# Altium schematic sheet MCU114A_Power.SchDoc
size 431 x 279 mm; Date: Not shown in title block; ApprovedBy: Not shown in title block; CheckedBy: Not shown in title block; Author: Not shown in title block; CompanyName: Not shown in title block; Engineer: Not shown in title block; Organization: Not shown in title block; Address1: Not shown in title block; Address2: Not shown in title block; Address3: Not shown in title block; Address4: Not shown in title block; DocumentNumber: 5; Revision: Use project parameter SCH_Rev; SheetNumber: 5; SheetTotal: 11; PageSetup: Record=PageOptions¦CenterHorizontal=True¦CenterVertical=True¦PrintScale=1.00¦XCorrection=1.00¦YCorrection=1.00¦PrintKind=0¦BorderSize=5000000¦LeftOffset=0¦BottomOffset=0¦Orientation=2¦PaperLength=1000¦PaperWidth=1000¦Scale=100¦PaperSource=15¦PrintQuality=600¦MediaType=1¦DitherType=10¦PaperKind=Letter¦PrintScaleMode=1
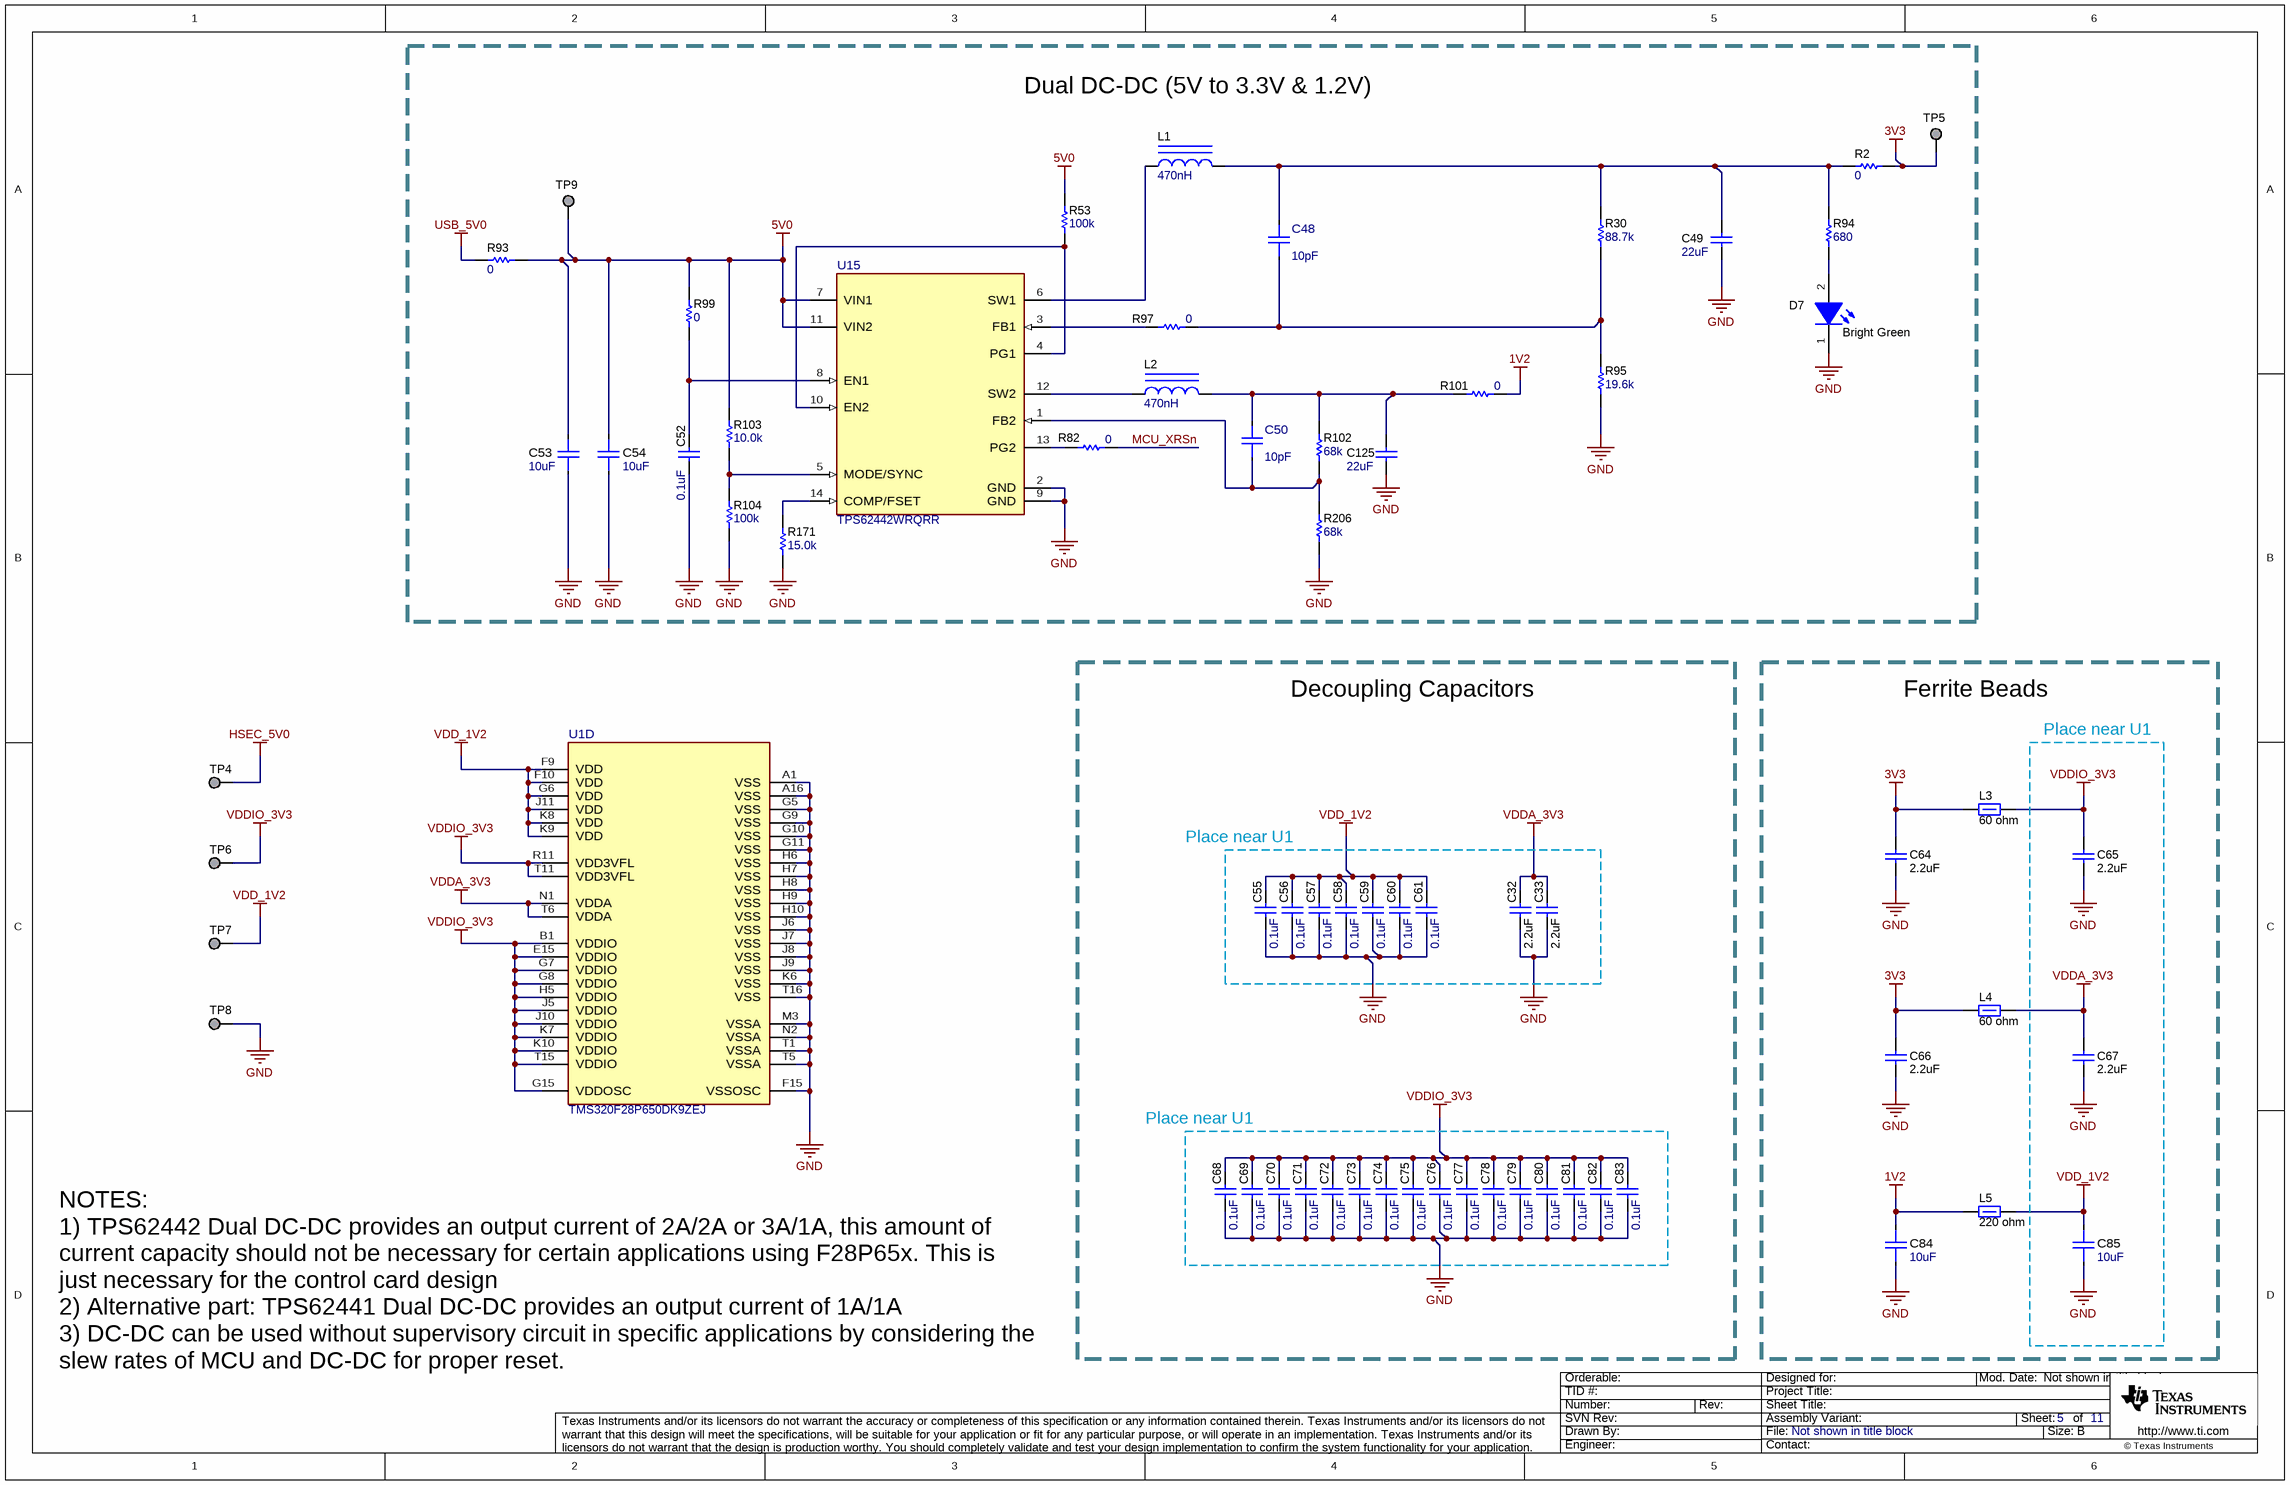
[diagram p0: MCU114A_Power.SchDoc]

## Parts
C32  ValueDisplayed: 2.2uF  [0603]  (hidden comment: 885012106018)
C33  ValueDisplayed: 2.2uF  [0603]  (hidden comment: 885012106018)
C48  ValueDisplayed: 10pF  [FP-885012006032_0603-MFG]  (hidden comment: 885012006032)
C49  ValueDisplayed: 22uF  [0603]  (hidden comment: GRM188R61A226ME15D)
C50  ValueDisplayed: 10pF  [FP-885012006032_0603-MFG]  (hidden comment: 885012006032)
C52  ValueDisplayed: 0.1uF  [0402]  (hidden comment: 885012205037)
C53  ValueDisplayed: 10uF  [FP-CC0603KRX5R7BB106_0603-MFG]  (hidden comment: CC0603KRX5R7BB106)
C54  ValueDisplayed: 10uF  [FP-CC0603KRX5R7BB106_0603-MFG]  (hidden comment: CC0603KRX5R7BB106)
C55  ValueDisplayed: 0.1uF  [0402]  (hidden comment: 885012205037)
C56  ValueDisplayed: 0.1uF  [0402]  (hidden comment: 885012205037)
C57  ValueDisplayed: 0.1uF  [0402]  (hidden comment: 885012205037)
C58  ValueDisplayed: 0.1uF  [0402]  (hidden comment: 885012205037)
C59  ValueDisplayed: 0.1uF  [0402]  (hidden comment: 885012205037)
C60  ValueDisplayed: 0.1uF  [0402]  (hidden comment: 885012205037)
C61  ValueDisplayed: 0.1uF  [0402]  (hidden comment: 885012205037)
C64  ValueDisplayed: 2.2uF  [0603]  (hidden comment: 885012106018)
C65  ValueDisplayed: 2.2uF  [0603]  (hidden comment: 885012106018)
C66  ValueDisplayed: 2.2uF  [0603]  (hidden comment: 885012106018)
C67  ValueDisplayed: 2.2uF  [0603]  (hidden comment: 885012106018)
C68  ValueDisplayed: 0.1uF  [0402]  (hidden comment: 885012205037)
C69  ValueDisplayed: 0.1uF  [0402]  (hidden comment: 885012205037)
C70  ValueDisplayed: 0.1uF  [0402]  (hidden comment: 885012205037)
C71  ValueDisplayed: 0.1uF  [0402]  (hidden comment: 885012205037)
C72  ValueDisplayed: 0.1uF  [0402]  (hidden comment: 885012205037)
C73  ValueDisplayed: 0.1uF  [0402]  (hidden comment: 885012205037)
C74  ValueDisplayed: 0.1uF  [0402]  (hidden comment: 885012205037)
C75  ValueDisplayed: 0.1uF  [0402]  (hidden comment: 885012205037)
C76  ValueDisplayed: 0.1uF  [0402]  (hidden comment: 885012205037)
C77  ValueDisplayed: 0.1uF  [0402]  (hidden comment: 885012205037)
C78  ValueDisplayed: 0.1uF  [0402]  (hidden comment: 885012205037)
C79  ValueDisplayed: 0.1uF  [0402]  (hidden comment: 885012205037)
C80  ValueDisplayed: 0.1uF  [0402]  (hidden comment: 885012205037)
C81  ValueDisplayed: 0.1uF  [0402]  (hidden comment: 885012205037)
C82  ValueDisplayed: 0.1uF  [0402]  (hidden comment: 885012205037)
C83  ValueDisplayed: 0.1uF  [0402]  (hidden comment: 885012205037)
C84  ValueDisplayed: 10uF  [FP-CC0603KRX5R7BB106_0603-MFG]  (hidden comment: CC0603KRX5R7BB106)
C85  ValueDisplayed: 10uF  [FP-CC0603KRX5R7BB106_0603-MFG]  (hidden comment: CC0603KRX5R7BB106)
C125  ValueDisplayed: 22uF  [0603]  (hidden comment: GRM188R61A226ME15D)
D7  value Bright Green  [WL-SMCW_Green_0805]  (hidden comment: 150080VS75000)
L1  ValueDisplayed: 470nH  [XFL4015]  (hidden comment: XFL4015-471MEC)
L2  ValueDisplayed: 470nH  [XFL4015]  (hidden comment: XFL4015-471MEC)
L3  60 ohm  [0805_HV]
L4  60 ohm  [0805_HV]
L5  220 ohm  [0805_HV]
R2  ValueDisplayed: 0  [0402]  (hidden comment: ERJ-2GE0R00X)
R30  ValueDisplayed: 88.7k  [0402]  (hidden comment: CRCW040288K7FKED)
R53  ValueDisplayed: 100k  [0603]  (hidden comment: CRCW0603100KJNEA)
R82  ValueDisplayed: 0  [0402]  (hidden comment: ERJ-2GE0R00X)
R93  ValueDisplayed: 0  [0402]  (hidden comment: ERJ-2GE0R00X)
R94  ValueDisplayed: 680  [0402]  (hidden comment: CRCW0402680RJNED)
R95  ValueDisplayed: 19.6k  [0402]  (hidden comment: CRCW040219K6FKED)
R97  ValueDisplayed: 0  [0402]  (hidden comment: ERJ-2GE0R00X)
R99  ValueDisplayed: 0  [0402]  (hidden comment: ERJ-2GE0R00X)
R101  ValueDisplayed: 0  [0402]  (hidden comment: ERJ-2GE0R00X)
R102  ValueDisplayed: 68k  [0402]  (hidden comment: CRCW040268K0JNED)
R103  ValueDisplayed: 10.0k  [0402]  (hidden comment: AC0402FR-0710KL)
R104  ValueDisplayed: 100k  [0603]  (hidden comment: CRCW0603100KJNEA)
R171  ValueDisplayed: 15.0k  [0402]  (hidden comment: CRCW040215K0FKED)
R206  ValueDisplayed: 68k  [0402]  (hidden comment: CRCW040268K0JNED)
TP4  TESTPOINT  [TP_50MIL-25MILHOLE]  (value not drawn)  (no BOM)
TP5  TESTPOINT  [TP_50MIL-25MILHOLE]  (value not drawn)  (no BOM)
TP6  TESTPOINT  [TP_50MIL-25MILHOLE]  (value not drawn)  (no BOM)
TP7  TESTPOINT  [TP_50MIL-25MILHOLE]  (value not drawn)  (no BOM)
TP8  TESTPOINT  [TP_50MIL-25MILHOLE]  (value not drawn)  (no BOM)
TP9  TESTPOINT  [TP_50MIL-25MILHOLE]  (value not drawn)  (no BOM)
U1  TMS320F28P650DK9ZEJ  [ZEJ0256A-MFG]  (part D of 4)
U15  TPS62442WRQRR  [RQR0014A-MFG]

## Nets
1V2: C84.2 L5.1 R101.2
3V3: C64.1 C66.1 L3.1 L4.1 R2.2 TP5.1
5V0: C53.2 C54.2 R53.2 R93.2 R99.2 R103.2 TP9.1 U15.7(VIN1) U15.11(VIN2)
GND: C32.2 C33.2 C49.2 C52.1 C53.1 C54.1 C55.2 C56.2 C57.2 C58.2 C59.2 C60.2 C61.2 C64.2 C65.2 C66.2 C67.2 C68.2 C69.2 C70.2 C71.2 C72.2 C73.2 C74.2 C75.2 C76.2 C77.2 C78.2 C79.2 C80.2 C81.2 C82.2 C83.2 C84.1 C85.1 C125.2 D7.1(K) R95.1 R104.1 R171.1 R206.1 TP8.1 U1.A1(VSS) U1.A16(VSS) U1.F15(VSSOSC) U1.G5(VSS) U1.G9(VSS) U1.G10(VSS) U1.G11(VSS) U1.H6(VSS) U1.H7(VSS) U1.H8(VSS) U1.H9(VSS) U1.H10(VSS) U1.J6(VSS) U1.J7(VSS) U1.J8(VSS) U1.J9(VSS) U1.K6(VSS) U1.M3(VSSA) U1.N2(VSSA) U1.T1(VSSA) U1.T5(VSSA) U1.T16(VSS) U15.2(GND) U15.9(GND)
HSEC_5V0: TP4.1
USB_5V0: R93.1
VDD_1V2: C55.1 C56.1 C57.1 C58.1 C59.1 C60.1 C61.1 C85.2 L5.2 TP7.1 U1.F9(VDD) U1.F10(VDD) U1.G6(VDD) U1.J11(VDD) U1.K8(VDD) U1.K9(VDD)
VDDA_3V3: C32.1 C33.1 C67.1 L4.2 U1.N1(VDDA) U1.T6(VDDA)
VDDIO_3V3: C65.1 C68.1 C69.1 C70.1 C71.1 C72.1 C73.1 C74.1 C75.1 C76.1 C77.1 C78.1 C79.1 C80.1 C81.1 C82.1 C83.1 L3.2 TP6.1 U1.B1(VDDIO) U1.E15(VDDIO) U1.G7(VDDIO) U1.G8(VDDIO) U1.G15(VDDOSC) U1.H5(VDDIO) U1.J5(VDDIO) U1.J10(VDDIO) U1.K7(VDDIO) U1.K10(VDDIO) U1.R11(VDD3VFL) U1.T11(VDD3VFL) U1.T15(VDDIO)
MCU_XRSn: R82.2
NetC48_1: C48.1 R30.1 R95.2 R97.2
NetC48_2: C48.2 C49.1 L1.2 R2.1 R30.2 R94.2
NetC50_1: C50.1 R102.1 R206.2 U15.1(FB2)
NetC50_2: C50.2 C125.1 L2.2 R101.1 R102.2
NetC52_2: C52.2 R99.1 U15.8(EN1)
NetD7_2: D7.2(A) R94.1
NetL1_1: L1.1 U15.6(SW1)
NetL2_1: L2.1 U15.12(SW2)
NetR53_1: R53.1 U15.4(PG1) U15.10(EN2)
NetR82_1: R82.1 U15.13(PG2)
NetR97_1: R97.1 U15.3(FB1)
NetR103_1: R103.1 R104.2 U15.5(MODE/SYNC)
NetR171_2: R171.2 U15.14(COMP/FSET)

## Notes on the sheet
- Dual DC-DC (5V to 3.3V & 1.2V)
- Decoupling Capacitors
- Ferrite Beads
- Place near U1
- NOTES:
  1) TPS62442 Dual DC-DC provides an output current of 2A/2A or 3A/1A, this amount of current capacity should not be necessary for certain applications using F28P65x. This is just necessary for the control card design
  2) Alternative part: TPS62441 Dual DC-DC provides an output current of 1A/1A
  3) DC-DC can be used without supervisory circuit in specific applications by considering the slew rates of MCU and DC-DC for proper reset.

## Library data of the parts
C32 C33 C64-C67 = CMP-0006825-5: CAP, CERM, 2.2 uF, 16 V, +/- 20%, X5R, 0603; Manufacturer: Wurth Elektronik; TaMin_C: -55°C; Polarized: N; SizeAreaWB_mm2: 4.68; Value1: Unknown; U/M: EA; Value: 2.2uF; TaMax_C: 85°C; SizeZ_mm: 1; SizeX_mm: 1.6; SizeY_mm: 0.8; Value2: 16V; SizeArea_mm2: 1.28; Cap_F: 2.2µF; AEC Category: Q200
C48 C50 = CMP-0096972-1: 10 pF ±5% 25V Ceramic Capacitor C0G, NP0 0603 (1608 Metric); Manufacturer: Wurth Electronics; Value: 10pF; AEC Qualified: No; TempCo: 30ppm/°C; SizeZ_mm: 0.87mm
C49 C125 = CMP-0007324-5: CAP, CERM, 22 uF, 10 V, +/- 20%, X5R, 0603; Manufacturer: MuRata; TaMin_C: -55°C; Polarized: N; SizeAreaWB_mm2: 4.68; Value1: Unknown; U/M: EA; Value: 22uF; TaMax_C: 85°C; SizeZ_mm: 1; SizeX_mm: 1.6; SizeY_mm: 0.8; Value2: 10V; SizeArea_mm2: 1.28; Cap_F: 22µF; AEC Category: Q200
C52 C55-C61 C68-C83 = CMP-0006228-2: CAP, CERM, 0.1 uF, 16 V, +/- 10%, X7R, 0402; Manufacturer: Wurth Elektronik; TaMin_C: -55°C; Polarized: N; SizeAreaWB_mm2: 3; Value1: Unknown; U/M: EA; Value: 0.1uF; TaMax_C: 125°C; SizeZ_mm: 0.6; SizeX_mm: 1; SizeY_mm: 0.5; Value2: 16V; Cap_F: 100nF; AEC Category: Q200
C53 C54 C84 C85 = CMP-0001560-1: Multilayer Ceramic Capacitors 10uF 16V X5R 10% SMD 0603 85°C Paper T/R - Tape an; Manufacturer: Yageo; AEC Qualified: No; Cap_F: 10µF; SizeZ_mm: 1mm; TempCo: 15%; Value: 10µF
D7 = CMP-0002960-2: LED, Bright Green, SMD; Manufacturer: Wurth Elektronik; Type: AlInGaP; Vf_V: 2V; Io_A: 20mA; Vr_V: 5V; Tjmax_C: 85°C; Power_TotalModule: 72mW; Value1: 0.072W; Angle: 140; U/M: EA
L1 L2 = CMP-0061147-1: Inductor, Shielded, Composite, 470 nH, 3.5 A, 0.0076 ohm, SMD; Manufacturer: Coilcraft; Isat: 3.5A @ 10% inductance drop; Irms: 9.1A @ 20C rise; Green_Lifecycle: Not Set; SizeAreaWB_mm2: 28.09; DCR_ohm: 7.6m; Green_REACh: Incomplete; Value: 470nH; Imax_A: 3.5A; SizeZ_mm: 1.6; SizeX_mm: 4.3; SizeArea_mm2: 18.49; AEC Category: Q200
L3 L4 = CMP-0003093-1: Ferrite Bead, 60 ohm @ 100 MHz, 3 A, 0805; Manufacturer: Wurth Elektronik; PartNumber: 742792063; Ztyp@1GHz_Ohm: 95.384; ZTyp@100MHz_Ohm: 60; SizeAreaWB_mm2: 6.75; DCR_ohm: 0.025; Value1: 0.025 ohm; Imax_A: 3A; SizeZ_mm: 1.45; SizeX_mm: 2; SizeY_mm: 1.25; SizeArea_mm2: 2.5
L5 = CMP-0003073-1: Ferrite Bead, 220 ohm @ 100 MHz, 2 A, 0805; Manufacturer: Wurth Elektronik; PartNumber: 742792022; Ztyp@1GHz_Ohm: 190.289; ZTyp@100MHz_Ohm: 220; SizeAreaWB_mm2: 6.75; DCR_ohm: 0.05; Value1: 0.05 ohm; Imax_A: 2A; SizeZ_mm: 1.45; SizeX_mm: 2; SizeY_mm: 1.25; SizeArea_mm2: 2.5
R2 R82 R93 R97 R99 R101 = CMP-0026992-3: RES, 0, 5%, 0.1 W, AEC-Q200 Grade 0, 0402; Manufacturer: Panasonic; Power_W: 100mW; TempCo: 600 ppm/C; Value_Code: 0000; Value: 0; EIA_Code: E24; SizeX_mm: 1; SizeY_mm: 0.5; SizeZ_mm: 0.6; Value2: 0.1W; AEC Qualified: Y; VDC_V: 50V; AEC Category: Q200; SizeAreaWB_mm2: 3
R30 = CMP-0026586-2: RES, 88.7 k, 1%, 0.063 W, AEC-Q200 Grade 0, 0402; Manufacturer: Vishay-Dale; Power_W: 63mW; TempCo: 100 ppm/C; Value_Code: 88k7; Value: 88.7k; EIA_Code: E96; SizeX_mm: 1; SizeY_mm: 0.5; SizeZ_mm: 0.6; Value2: 0.063W; AEC Qualified: Y; VDC_V: 50V; AEC Category: Q200; AEC Grade: 0
R53 R104 = CMP-0025698-4: RES, 100 k, 5%, 0.1 W, AEC-Q200 Grade 0, 0603; Manufacturer: Vishay-Dale; Power_W: 100mW; TempCo: 200 ppm/C; Value: 100k; EIA_Code: E24; SizeX_mm: 1.6; SizeY_mm: 0.8; SizeZ_mm: 1; Value2: 0.1W; SizeArea_mm2: 1.28; AEC Qualified: Y; VDC_V: 75V; AEC Category: Q200; AEC Grade: 0
R94 = CMP-0026962-3: RES, 680, 5%, 0.063 W, AEC-Q200 Grade 0, 0402; Manufacturer: Vishay-Dale; Power_W: 63mW; TempCo: 200 ppm/C; Value_Code: 680R; Value: 680; EIA_Code: E24; SizeX_mm: 1; SizeY_mm: 0.5; SizeZ_mm: 0.6; Value2: 0.063W; AEC Qualified: Y; VDC_V: 50V; AEC Category: Q200; AEC Grade: 0
R95 = CMP-0026068-3: RES, 19.6 k, 1%, 0.063 W, AEC-Q200 Grade 0, 0402; Manufacturer: Vishay-Dale; Power_W: 63mW; TempCo: 100 ppm/C; Value_Code: 19k6; Value: 19.6k; EIA_Code: E96; SizeX_mm: 1; SizeY_mm: 0.5; SizeZ_mm: 0.6; Value2: 0.063W; AEC Qualified: Y; VDC_V: 50V; AEC Category: Q200; AEC Grade: 0
R102 R206 = CMP-0026963-3: RES, 68 k, 5%, 0.063 W, AEC-Q200 Grade 0, 0402; Manufacturer: Vishay-Dale; Power_W: 63mW; TempCo: 200 ppm/C; Value_Code: 68k0; Value: 68k; EIA_Code: E24; SizeX_mm: 1; SizeY_mm: 0.5; SizeZ_mm: 0.6; Value2: 0.063W; AEC Qualified: Y; VDC_V: 50V; AEC Category: Q200; AEC Grade: 0
R103 = CMP-0077731-1: RES, 10.0 k, 1%, 0.063 W, AEC-Q200 Grade 0, 0402; Manufacturer: Yageo America; Power_W: 63mW; TempCo: 100 ppm/C; Value_Code: 10k0; U/M: EA; Value: 10.0k; EIA_Code: E96; Res_ohm: 10k; SizeX_mm: 1.0; SizeY_mm: 0.5; SizeZ_mm: 0.6; Value2: 0.063W; AEC Qualified: Y; VDC_V: 50V; AEC Grade: 0; AEC Category: Q200
R171 = CMP-0026027-3: RES, 15.0 k, 1%, 0.063 W, AEC-Q200 Grade 0, 0402; Manufacturer: Vishay-Dale; Power_W: 63mW; TempCo: 100 ppm/C; Value_Code: 15k0; Value: 15.0k; EIA_Code: E96; Res_ohm: 15k; SizeX_mm: 1; SizeY_mm: 0.5; SizeZ_mm: 0.6; Value2: 0.063W; AEC Qualified: Y; VDC_V: 50V; AEC Category: Q200; AEC Grade: 0
TP4-TP9 = CMP-0078143-3: TEST POINT.  No entry in BOM.
U1 = CMP-0096042-2: Real-Time Microcontroller NFBGA256; Manufacturer: Texas Instruments; AEC Category: Q200; Core Architecture: C28x; Data Bus Width: 32bits; Number Of Ethernet Channels: 1; Number Of Cores: 2; CompType: IC; Number Of I/Os: 159; Interface: I2C,SPI,UART,CAN,USB,LIN,SCI,Ethernet,Other; Number Of Pwm Channels: 36; AEC Qualified: No; Number Of Timers/Counters: 6; Standoff Height: 0.35mm; Number Of Spi Channels: 4; SizeZ_mm: 1.4mm; Number Of Adc Channels: 40; Ram Size: 248KBytes; Frequency_Fixed: 200MHz; Memory Size: 1.28MBytes; Number Of A/D Converters: 3; Memory Type: FLASH
U15 = CMP-0094192-1: 2.7-V to 6-V Adjustable-Frequency Dual Step-Down Converter in QFN package; Manufacturer: Texas Instruments; Number Of Outputs: 2; Max Duty Cycle: 100%; TaMin_C: -40°C; Standoff Height: 0mm; AEC Grade: NA; AEC Qualified: No; Output Type: AdjustableProgrammable; Max Supply Voltage: 6V; Min Supply Voltage: 2.7V; TaMax_C: +125°C; SizeZ_mm: 1mm; Switching Topology: Buck; TJmax_C: +150°C; Output Voltage: 0.6-5.5V; Nominal Supply Current: 22-33uA; Switching Frequency: 1.8-4MHz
